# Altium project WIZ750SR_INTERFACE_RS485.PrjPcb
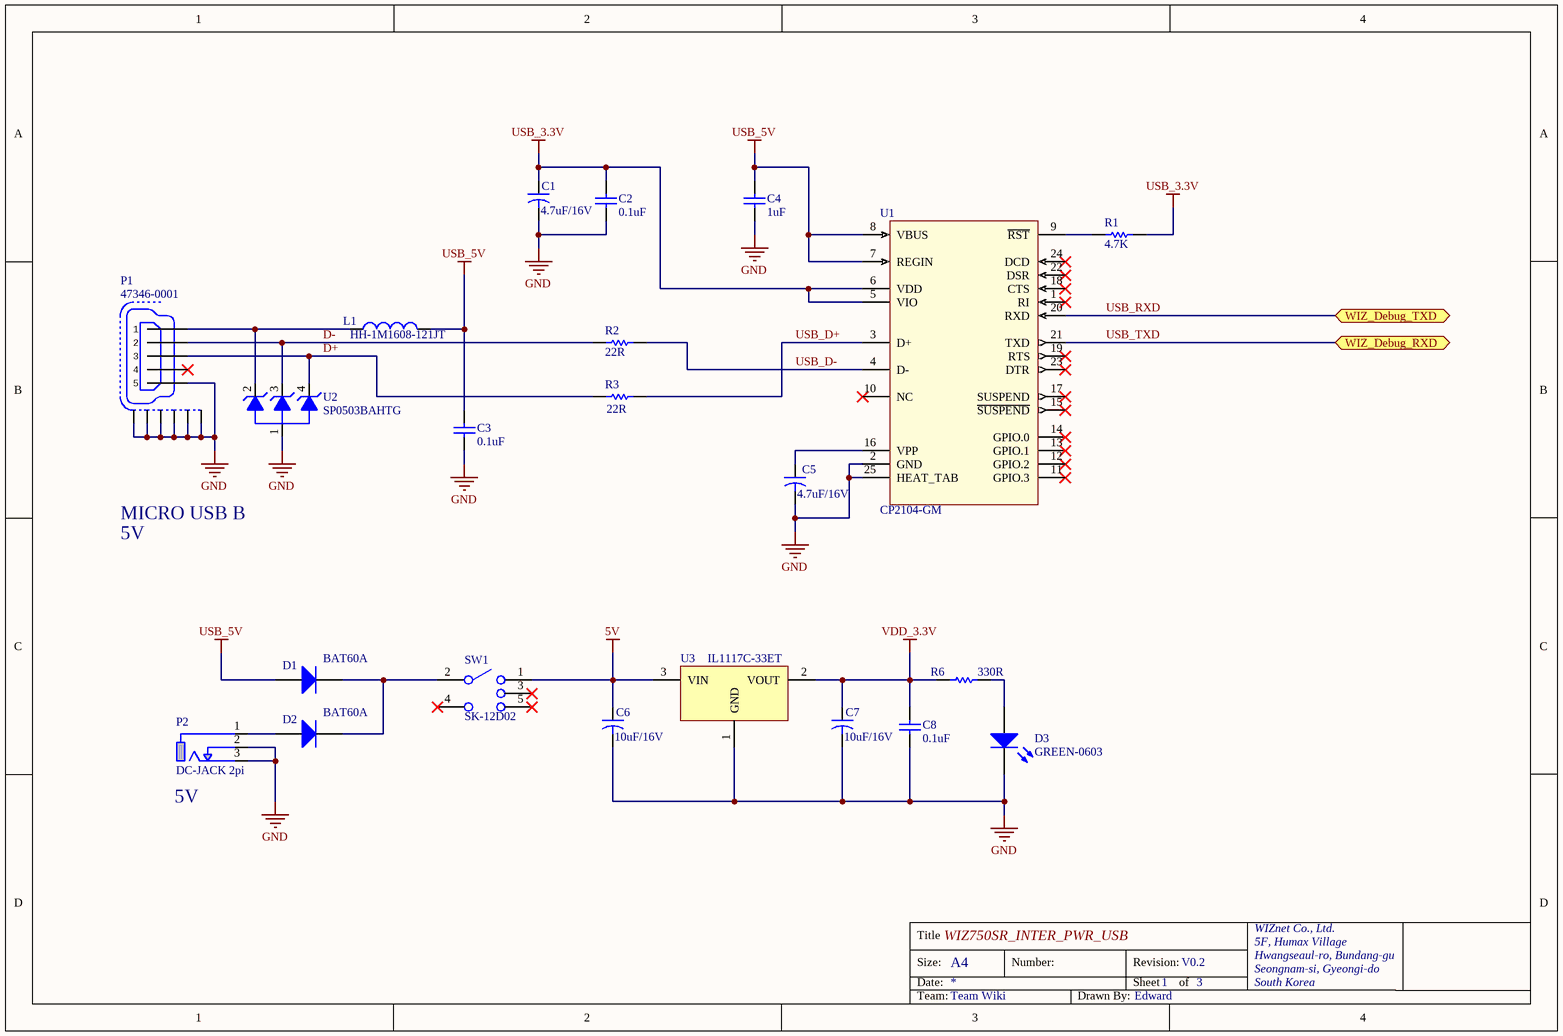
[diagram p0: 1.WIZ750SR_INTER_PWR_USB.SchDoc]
3 sheets, 59 parts. Net scope: flat (ports and power ports of the same name join across sheets).
Board file: WIZ750SR_INTERFACE_RS485.PcbDoc
Sheets:
  1.WIZ750SR_INTER_PWR_USB.SchDoc
  2.WIZ750SR_INTER_CON.SchDoc
  3.WIZ750SR_INTER_ETC.SchDoc

## Sheet 1.WIZ750SR_INTER_PWR_USB.SchDoc
size A4; DrawnBy: Peter; Organization: WIZnet Co., Ltd.; Address1: 5F, Humax Village; Address2: Hwangseaul-ro, Bundang-Gu; Address3: Seongnam-Si, Gyeonggi-Do; Address4: South Korea; Team: Wiki

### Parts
C1  4.7uF/16V  [CAP-A Size]
C2  0.1uF  [CAP-0603]
C3  0.1uF  [CAP-0603]
C4  1uF  [CAP-0603]
C5  4.7uF/16V  [CAP-A Size]
C6  10uF/16V  [CAP-A Size]
C7  10uF/16V  [CAP-A Size]
C8  0.1uF  [CAP-0603]
D1  BAT60A  [D-BAT60A/SOD-323]
D2  BAT60A  [D-BAT60A/SOD-323]
D3  GREEN-0603  [LED-0603-RED]
L1  HH-1M1608-121JT  [IND-0603]
P1  47346-0001  [USB-MICRO-B(SMD)]
P2  DC-JACK 2pi  [DC-JACK 2pi]
R1  4.7K  [RES-0603]
R2  22R  [RES-0603]
R3  22R  [RES-0603]
R6  330R  [RES-0603]
SW1  SK-12D02  [SK-12D02]
U1  CP2104-GM  [CP2104_QFN24_PAD]
U2  SP0503BAHTG  [SP0503BAHTG]
U3  IL1117C-33ET  [IL1117C-33ET]

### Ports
WIZ_Debug_RXD, WIZ_Debug_TXD

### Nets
5V: C6.1 SW1.1 U3.3(VIN)
GND: C1.2 C2.1 C3.1 C4.1 C5.2 C6.2 C7.2 C8.1 D3.2(K) P1.5 P1.6 P1.7 P1.8 P1.9 P1.10 P1.11 P2.2(GND) P2.3(GND) U1.2(GND) U1.25(HEAT_TAB) U2.1 U3.1(GND)
USB_3.3V: C1.1 C2.2 R1.2 U1.5(VIO) U1.6(VDD)
USB_5V: C3.2 C4.2 D1.2(A) L1.2 U1.7(REGIN) U1.8(VBUS)
VDD_3.3V: C7.1 C8.2 R6.1 U3.2(VOUT)
D+: P1.3 R3.1 U2.4
D-: P1.2 R2.1 U2.3
USB_D+: R3.2 U1.3(D+)
USB_D-: R2.2 U1.4(D-)
USB_RXD: U1.20(RXD) ; port WIZ_Debug_TXD  [project net U_TXD]
USB_TXD: U1.21(TXD) ; port WIZ_Debug_RXD  [project net U_RXD]
NetC5_1: C5.1 U1.16(VPP)
NetD1_1: D1.1(K) D2.1(K) SW1.2
NetD2_2: D2.2(A) P2.1(VCC)
NetD3_1: D3.1(A) R6.2
NetL1_1: L1.1 P1.1 U2.2
NetR1_1: R1.1 U1.9(~{RST})

Not connected (* = marked no-connect by the designer): P1 4*; SW1 3* 4* 5*; U1 1(RI)* 10(NC)* 11(GPIO.3)* 12(GPIO.2)* 13(GPIO.1)* 14(GPIO.0)* 15(~{SUSPEND})* 17(SUSPEND)* 18(CTS)* 19(RTS)* 22(DSR)* 23(DTR)* 24(DCD)*

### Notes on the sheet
- MICRO USB B
- 5V
- (near P2) 5V
- Title
- Size:
- Date:
- WIZ750SR_INTER_PWR_USB
- A4
- Number:
- Revision:
- Sheet
- 1
- of
- V0.2
- 3
- WIZnet Co., Ltd.
- 5F, Humax Village
- Hwangseaul-ro, Bundang-gu
- Seongnam-si, Gyeongi-do
- South Korea
- Team:
- Team Wiki
- Drawn By:
- Edward

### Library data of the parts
C1 C5-C7 = CAP-A Size: Tantla CAP A Size EIA/IECQ 3216
C2-C4 C8 = CAP-0603: Ceramic CAP 0603(1608)
D1 D2 = DIODE-BAT60A: Silicon Schottky Diode
D3 = LED-0603
L1 = IND-0603: Inductor 0603(1608)
P1 = 47346-0001: MICRO USB B Type
R1-R3 R6 = RES-0603
SW1 = SK-12D02: 3 Port SW , SPDT ON-ON , 50V, 0.3A
U1 = CP2104-GM: USB to UART Bridge, SiliconLabs
U2 = SP0503BAHTG: Little Fuse, Silicon Protection Array Products
U3 = IL1117C-33ET: 1A, 3.3V

## Sheet 2.WIZ750SR_INTER_CON.SchDoc
size A4; DrawnBy: Peter; Organization: WIZnet Co., Ltd.; Address1: 5F, Humax Village; Address2: Hwangseaul-ro, Bundang-Gu; Address3: Seongnam-Si, Gyeonggi-Do; Address4: South Korea; Team: Wiki
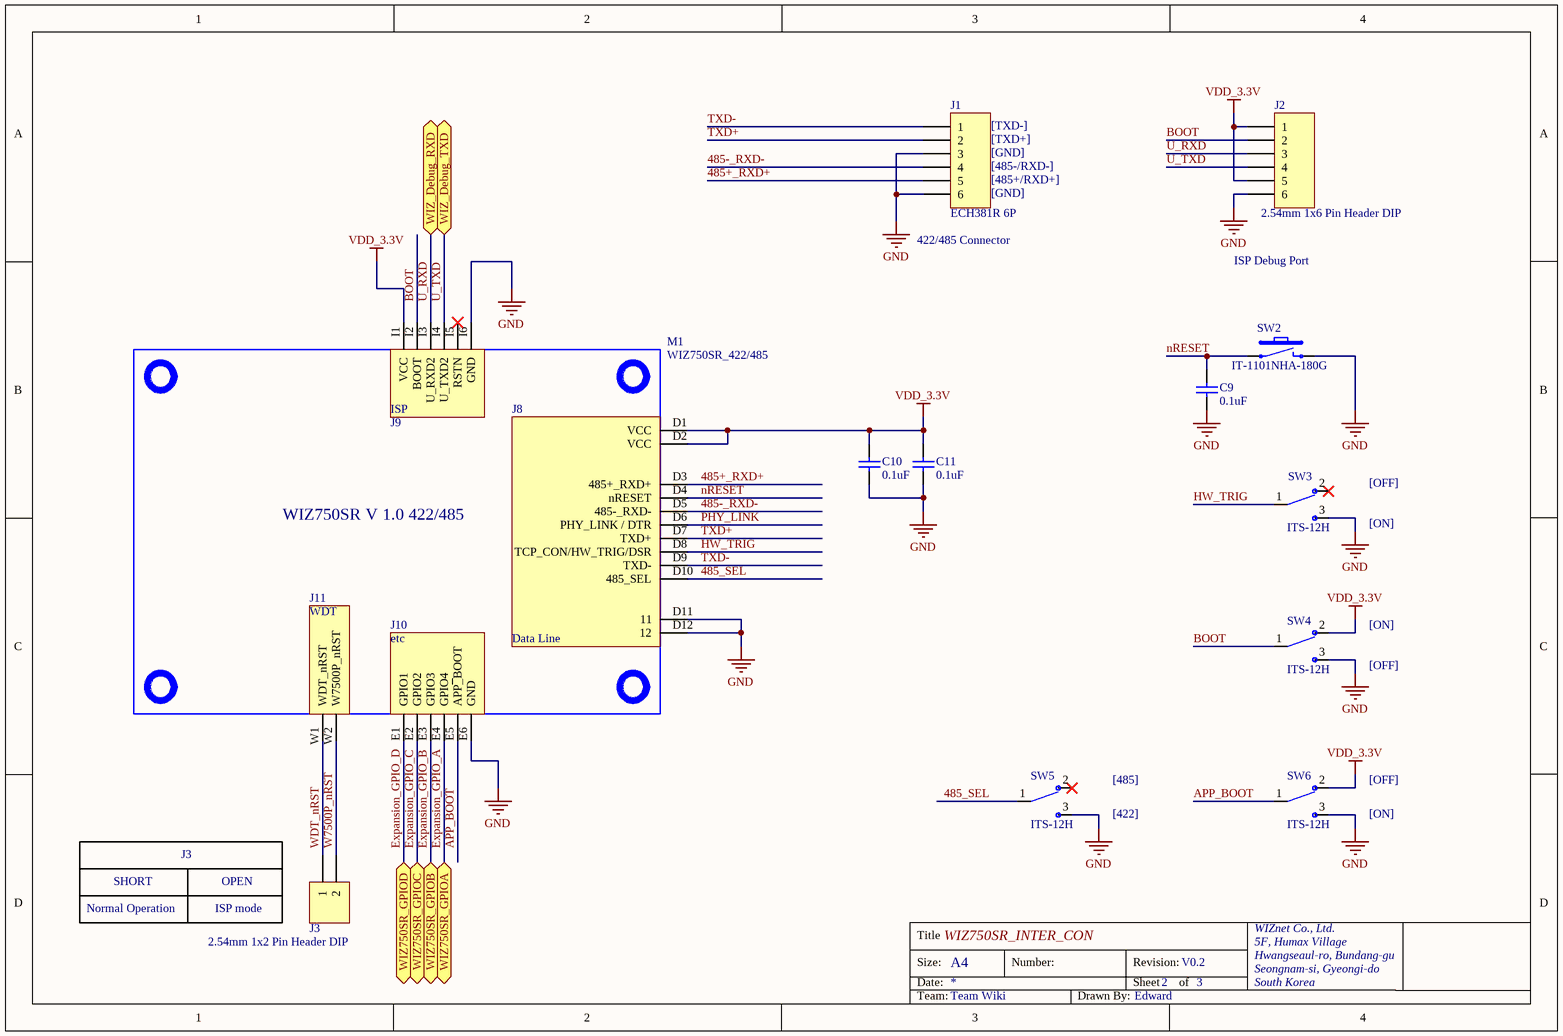
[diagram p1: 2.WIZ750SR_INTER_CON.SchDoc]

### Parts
C9  0.1uF  [CAP-0603]
C10  0.1uF  [CAP-0603]
C11  0.1uF  [CAP-0603]
J1  ECH381R 6P  [ECH381R_6P]
J2  2.54mm 1x6 Pin Header DIP  [IDC-1X6]
J3  2.54mm 1x2 Pin Header DIP  [IDC-1X2]
M1  WIZ750SR_422/485  [WIZ750SR_V1.0_232/485]
SW2  IT-1101NHA-180G  [IT-1101NHA]
SW3  ITS-12H  [ITS-12H]
SW4  ITS-12H  [ITS-12H]
SW5  ITS-12H  [ITS-12H]
SW6  ITS-12H  [ITS-12H]

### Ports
WIZ750SR_GPIOA, WIZ750SR_GPIOB, WIZ750SR_GPIOC, WIZ750SR_GPIOD, WIZ_Debug_RXD, WIZ_Debug_TXD

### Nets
GND: C9.1 C10.1 C11.1 J1.3 J1.6 J2.6 M1.D11(11) M1.D12(12) M1.E6(GND) M1.I6(GND) SW2.2 SW3.3 SW4.3 SW5.3 SW6.3
VDD_3.3V: C10.2 C11.2 J2.1 J2.5 M1.D1(VCC) M1.D2(VCC) M1.I1(VCC) SW4.2 SW6.2
485+_RXD+: J1.5 M1.D3(485+_RXD+)
485-_RXD-: J1.4 M1.D5(485-_RXD-)
485_SEL: M1.D10(485_SEL) SW5.1
APP_BOOT: M1.E5(APP~{_}BOOT) SW6.1
BOOT: J2.2 M1.I2(BOOT) SW4.1
Expansion_GPIO_A: M1.E4(GPIO4) ; port WIZ750SR_GPIOA
Expansion_GPIO_B: M1.E3(GPIO3) ; port WIZ750SR_GPIOB
Expansion_GPIO_C: M1.E2(GPIO2) ; port WIZ750SR_GPIOC
Expansion_GPIO_D: M1.E1(GPIO1) ; port WIZ750SR_GPIOD
HW_TRIG: M1.D8(TCP_CON/HW_TRIG/DSR) SW3.1
nRESET: C9.2 M1.D4(nRESET) SW2.1
PHY_LINK: M1.D6(PHY_LINK_/_DTR)
TXD+: J1.2 M1.D7(TXD+)
TXD-: J1.1 M1.D9(TXD-)
U_RXD: J2.3 M1.I3(U_RXD2) ; port WIZ_Debug_RXD
U_TXD: J2.4 M1.I4(U_TXD2) ; port WIZ_Debug_TXD
W7500P_nRST: J3.2 M1.W2(W7500P_nRST)
WDT_nRST: J3.1 M1.W1(WDT_nRST)

Not connected (* = marked no-connect by the designer): M1 I5(RSTN)*; SW3 2*; SW5 2*

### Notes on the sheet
- (near J1) [485-/RXD-]
- (near J1) [TXD+]
- (near J1) [TXD-]
- (near J1) [GND]
- (near J1) 422/485 Connector
- (near J1) [485+/RXD+]
- ISP Debug Port
- (near M1) J9
- (near M1) J8
- [OFF]
- [ON]
- (near M1) J11
- (near M1) J10
- [485]
- [422]
- Normal Operation
- SHORT
- J3
- ISP mode
- OPEN
- Title
- Size:
- Date:
- WIZ750SR_INTER_CON
- A4
- Number:
- Revision:
- Sheet
- 2
- of
- V0.2
- 3
- WIZnet Co., Ltd.
- 5F, Humax Village
- Hwangseaul-ro, Bundang-gu
- Seongnam-si, Gyeongi-do
- South Korea
- Team:
- Team Wiki
- Drawn By:
- Edward

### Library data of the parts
C9-C11 = CAP-0603: Ceramic CAP 0603(1608)
J1 = ECH381R 6P: Headers(Sockets) for pluggable terminal blocks
J2 = Header 6: Header, 6-Pin
J3 = Header 2: Header, 2-Pin
M1 = WIZ750SR_V1.0_422/485: Serial to ethernet module, 45mmx30mm, 422/485
SW2 = IT-1101NHA-180G: TACT Switch (SMD)
SW3-SW6 = ITS-12H: Slide Switch

## Sheet 3.WIZ750SR_INTER_ETC.SchDoc
size A4; DrawnBy: Peter; Organization: WIZnet Co., Ltd.; Address1: 5F, Humax Village; Address2: Hwangseaul-ro, Bundang-Gu; Address3: Seongnam-Si, Gyeonggi-Do; Address4: South Korea; Team: Wiki
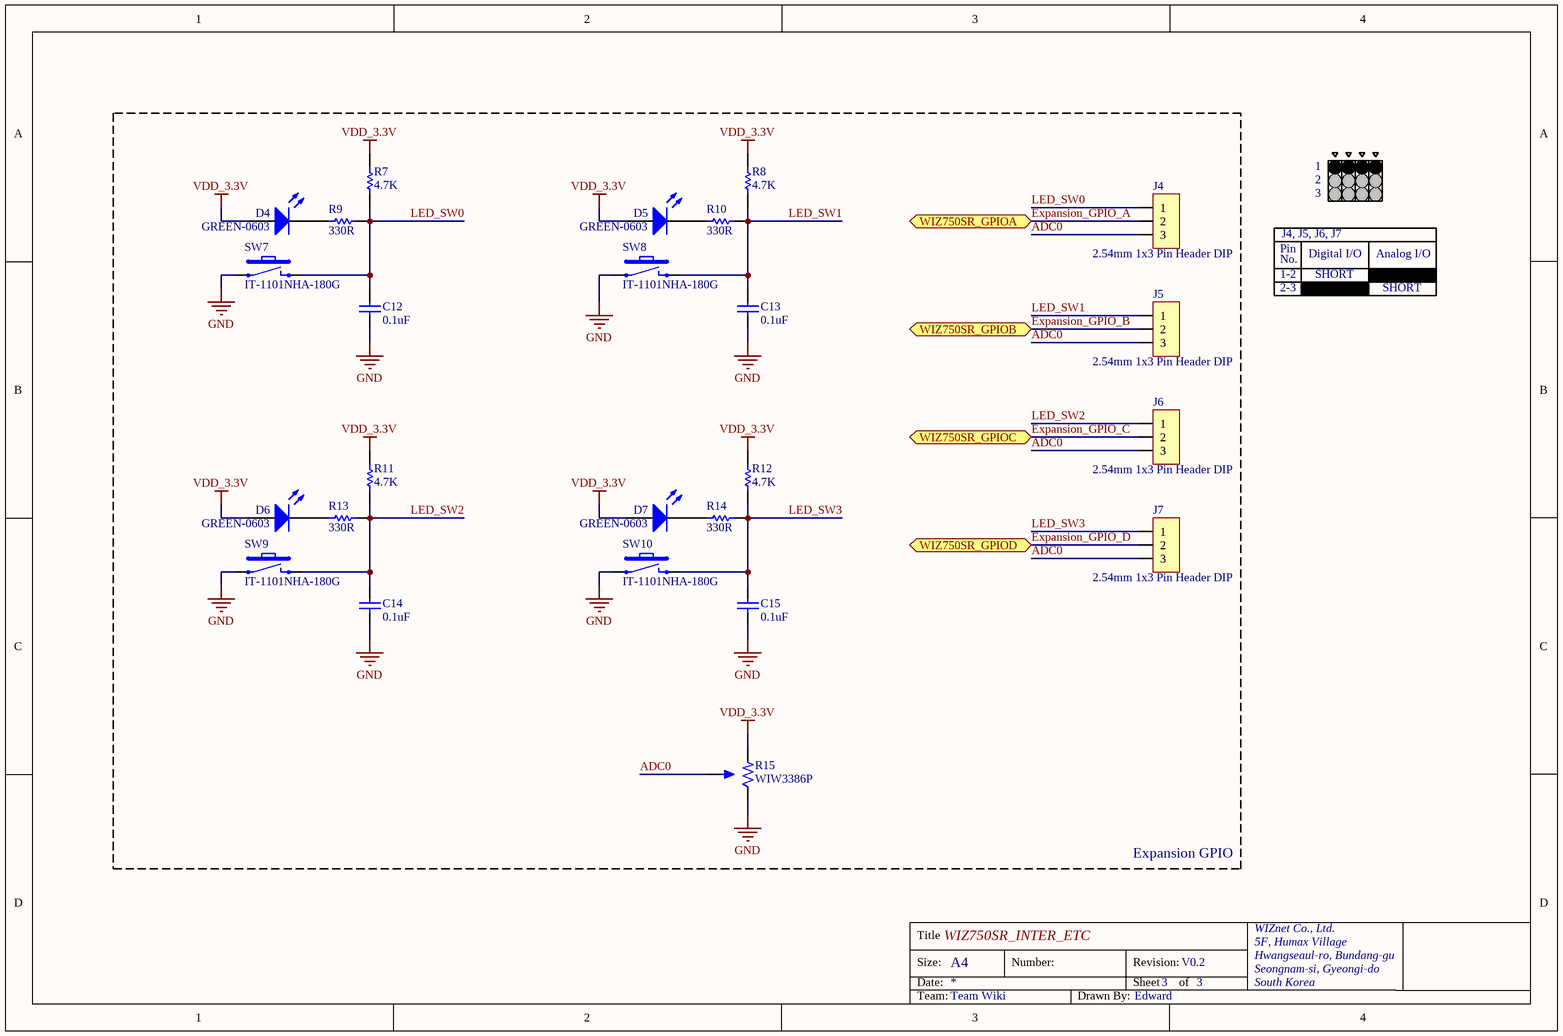
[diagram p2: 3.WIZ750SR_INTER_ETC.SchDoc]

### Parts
C12  0.1uF  [CAP-0603]
C13  0.1uF  [CAP-0603]
C14  0.1uF  [CAP-0603]
C15  0.1uF  [CAP-0603]
D4  GREEN-0603  [LED-0603-GREEN]
D5  GREEN-0603  [LED-0603-GREEN]
D6  GREEN-0603  [LED-0603-GREEN]
D7  GREEN-0603  [LED-0603-GREEN]
J4  2.54mm 1x3 Pin Header DIP  [IDC-1X3]
J5  2.54mm 1x3 Pin Header DIP  [IDC-1X3]
J6  2.54mm 1x3 Pin Header DIP  [IDC-1X3]
J7  2.54mm 1x3 Pin Header DIP  [IDC-1X3]
R7  4.7K  [RES-0603]
R8  4.7K  [RES-0603]
R9  330R  [RES-0603]
R10  330R  [RES-0603]
R11  4.7K  [RES-0603]
R12  4.7K  [RES-0603]
R13  330R  [RES-0603]
R14  330R  [RES-0603]
R15  WIW3386P  [WIW3386P]
SW7  IT-1101NHA-180G  [IT-1101NHA]
SW8  IT-1101NHA-180G  [IT-1101NHA]
SW9  IT-1101NHA-180G  [IT-1101NHA]
SW10  IT-1101NHA-180G  [IT-1101NHA]

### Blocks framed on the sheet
Expansion GPIO: C12-C15 D4-D7 J4-J7 R7-R15 SW7-SW10

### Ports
WIZ750SR_GPIOA, WIZ750SR_GPIOB, WIZ750SR_GPIOC, WIZ750SR_GPIOD

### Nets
GND: C12.1 C13.1 C14.1 C15.1 R15.3 SW7.1 SW8.1 SW9.1 SW10.1
VDD_3.3V: D4.1(A) D5.1(A) D6.1(A) D7.1(A) R7.2 R8.2 R11.2 R12.2 R15.1
ADC0: J4.3 J5.3 J6.3 J7.3 R15.2
Expansion_GPIO_A: J4.2 ; port WIZ750SR_GPIOA
Expansion_GPIO_B: J5.2 ; port WIZ750SR_GPIOB
Expansion_GPIO_C: J6.2 ; port WIZ750SR_GPIOC
Expansion_GPIO_D: J7.2 ; port WIZ750SR_GPIOD
LED_SW0: C12.2 J4.1 R7.1 R9.2 SW7.2
LED_SW1: C13.2 J5.1 R8.1 R10.2 SW8.2
LED_SW2: C14.2 J6.1 R11.1 R13.2 SW9.2
LED_SW3: C15.2 J7.1 R12.1 R14.2 SW10.2
NetD4_2: D4.2(K) R9.1
NetD5_2: D5.2(K) R10.1
NetD6_2: D6.2(K) R13.1
NetD7_2: D7.2(K) R14.1

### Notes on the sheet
- 1
- J4, J5, J6, J7
- 3
- 2
- Pin
- 1-2
- 2-3
- No.
- Digital I/O
- SHORT
- Analog I/O
- Title
- Size:
- Date:
- WIZ750SR_INTER_ETC
- A4
- Number:
- Revision:
- Sheet
- of
- V0.2
- WIZnet Co., Ltd.
- 5F, Humax Village
- Hwangseaul-ro, Bundang-gu
- Seongnam-si, Gyeongi-do
- South Korea
- Team:
- Team Wiki
- Drawn By:
- Edward

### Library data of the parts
C12-C15 = CAP-0603: Ceramic CAP 0603(1608)
D4-D7 = LED-0603
R7-R14 = RES-0603
R15 = WIW3386P: Potentiometer
SW7-SW10 = IT-1101NHA-180G: TACT Switch (SMD)

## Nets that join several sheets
GND: 1.WIZ750SR_INTER_PWR_USB (22 pins), 2.WIZ750SR_INTER_CON (15 pins), 3.WIZ750SR_INTER_ETC (9 pins)
VDD_3.3V: 1.WIZ750SR_INTER_PWR_USB (C7.1 C8.2 R6.1 U3.2), 2.WIZ750SR_INTER_CON (9 pins), 3.WIZ750SR_INTER_ETC (9 pins)
Expansion_GPIO_A: 2.WIZ750SR_INTER_CON (M1.E4), 3.WIZ750SR_INTER_ETC (J4.2)
Expansion_GPIO_B: 2.WIZ750SR_INTER_CON (M1.E3), 3.WIZ750SR_INTER_ETC (J5.2)
Expansion_GPIO_C: 2.WIZ750SR_INTER_CON (M1.E2), 3.WIZ750SR_INTER_ETC (J6.2)
Expansion_GPIO_D: 2.WIZ750SR_INTER_CON (M1.E1), 3.WIZ750SR_INTER_ETC (J7.2)
U_RXD: 1.WIZ750SR_INTER_PWR_USB (U1.21), 2.WIZ750SR_INTER_CON (J2.3 M1.I3)
U_TXD: 1.WIZ750SR_INTER_PWR_USB (U1.20), 2.WIZ750SR_INTER_CON (J2.4 M1.I4)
